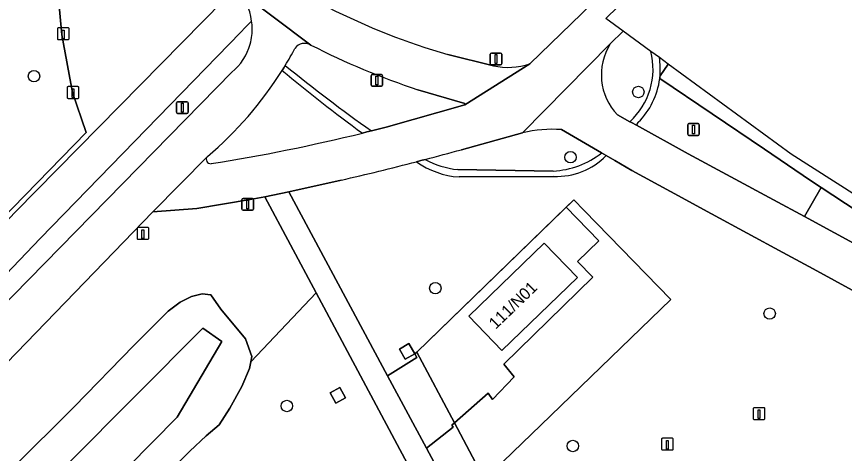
# Model space of a CAD drawing. Extents: x 155640 to 156811, y 382821 to 384049.
# Drawn here: x 156361.8 to 156432.6, y 383288.6 to 383326 of the extents above; entities that cross this region are included whole.
import ezdxf

# ---------------------------------------------------------------- set-up
doc = ezdxf.new("R2010")
doc.units = 0
for name, color, linetype in [('IMGEO_Berm_groen', 7, 'Continuous'), ('IMGEO_Boom', 7, 'Continuous'), ('IMGEO_Fietspad_gesloten', 7, 'Continuous'), ('IMGEO_Groenvoorziening', 7, 'Continuous'), ('IMGEO_Haag', 7, 'Continuous'), ('IMGEO_Hek', 7, 'Continuous'), ('IMGEO_Lichtmast', 7, 'Continuous'), ('IMGEO_Muur', 7, 'Continuous'), ('IMGEO_Oever', 7, 'Continuous'), ('IMGEO_Paal', 7, 'Continuous'), ('IMGEO_Pand', 7, 'Continuous'), ('IMGEO_Pand_nummerreeks', 7, 'Continuous'), ('IMGEO_Terreindeel_gesloten', 7, 'Continuous'), ('IMGEO_Verkeerseiland_groen', 7, 'Continuous'), ('IMGEO_Verkeerseiland_halfverhard', 7, 'Continuous'), ('IMGEO_Verkeerseiland_open', 7, 'Continuous'), ('IMGEO_Voetpad_gesloten', 7, 'Continuous'), ('IMGEO_Voetpad_onverhard', 7, 'Continuous'), ('IMGEO_Voetpad_open', 7, 'Continuous'), ('IMGEO_Waterloop', 7, 'Continuous')]:
    doc.layers.add(name, color=color, linetype=linetype)

msp = doc.modelspace()

# ---------------------------------------------------------------- linework, layer by layer
at = {"layer": 'IMGEO_Berm_groen'}
for points in [[(156381.892, 383325.599), (156381.348, 383325.039), (156380.959, 383324.639), (156363.82, 383307.004), (156337.443, 383279.37), (156311.15, 383251.521)], [(156360.181, 383300.803), (156380.194, 383321.217)], [(156361.434, 383287.344), (156366.724, 383292.604), (156371.834, 383297.853), (156374.748, 383300.784), (156375.78, 383301.56), (156376.759, 383302.039), (156377.674, 383302.264), (156378.399, 383302.193), (156379.248, 383300.961), (156381.369, 383298.415), (156381.897, 383296.903), (156381.815, 383296.443), (156387.41, 383302.346), (156383.014, 383310.578), (156381.78, 383310.334), (156377.211, 383309.584), (156373.432, 383309.293), (156346.778, 383281.729)]]:
    msp.add_lwpolyline(points, dxfattribs=at)
msp.add_lwpolyline([(156444.63, 383302.545), (156439.121, 383305.912), (156433.651, 383309.341), (156430.583, 383311.361), (156429.166, 383308.873), (156431.712, 383307.496), (156436.911, 383304.669), (156442.11, 383301.833), (156447.27, 383298.926), (156452.282, 383295.927), (156457.215, 383292.799), (156462.066, 383289.543), (156462.324, 383289.355), (156463.241, 383290.742), (156459.141, 383293.542), (156454.393, 383296.613), (156449.523, 383299.599)], close=True, dxfattribs=at)
for centre, radius, start, end in [((156377.156, 383324.92), 4.785, 353.42613, 8.16143), ((156377.193, 383324.912), 4.747, 344.44891, 353.47288), ((156377.133, 383324.925), 4.808, 309.53884, 344.48996)]:
    msp.add_arc(centre, radius, start, end, dxfattribs=at)
at = {"layer": 'IMGEO_Boom'}
for centre in [(156363.284, 383320.89), (156414.951, 383319.535), (156409.148, 383313.953), (156397.595, 383302.756), (156426.175, 383300.58), (156384.909, 383292.681), (156409.344, 383289.257)]:
    msp.add_circle(centre, 0.489, dxfattribs=at)
at = {"layer": 'IMGEO_Fietspad_gesloten'}
for points in [[(156413.66, 383324.737), (156412.178, 383325.823), (156505.069, 383416.138), (156504.846, 383416.367), (156503.871, 383417.37), (156412.253, 383328.349), (156411.874, 383327.981), (156405.667, 383321.95), (156400.124, 383318.442), (156393.394, 383316.534), (156392.135, 383316.212), (156391.748, 383316.116), (156391.361, 383316.02)], [(156363.724, 383341.638), (156369.095, 383337.403), (156379.009, 383329.585), (156379.648, 383329.081), (156380.504, 383328.406), (156386.96, 383323.552)], [(156386.96, 383323.552), (156380.504, 383328.406)], [(156399.819, 383314.599), (156405.049, 383316.037), (156412.539, 383323.648), (156413.66, 383324.737)], [(156412.539, 383323.648), (156405.049, 383316.037)], [(156402.557, 383321.777), (156398.667, 383322.745)], [(156396.11, 383319.733), (156400.129, 383318.562), (156400.124, 383318.442), (156405.667, 383321.95)], [(156380.194, 383321.217), (156360.181, 383300.803), (156343.328, 383283.312), (156320.142, 383258.454)], [(156384.5, 383321.375), (156384.634, 383321.592), (156384.768, 383321.81)], [(156471.432, 383282.388), (156466.787, 383286.102), (156462.324, 383289.355), (156462.066, 383289.543), (156457.215, 383292.799), (156452.282, 383295.927), (156447.27, 383298.926), (156442.11, 383301.833), (156436.911, 383304.669), (156431.712, 383307.496), (156429.166, 383308.873), (156426.506, 383310.311), (156419.216, 383314.26), (156414.78, 383316.686), (156414.359, 383316.916), (156414.222, 383316.991), (156413.154, 383317.575)], [(156408.386, 383316.322), (156411.813, 383314.329), (156412.207, 383314.099), (156412.93, 383313.678), (156414.393, 383312.827), (156417.685, 383311.033), (156421.201, 383309.128), (156427.301, 383305.816), (156429.889, 383304.414), (156435.055, 383301.593), (156440.217, 383298.767), (156445.339, 383295.87), (156450.27, 383292.91), (156455.125, 383289.825), (156459.799, 383286.696), (156464.349, 383283.389), (156469.029, 383279.65)], [(156322.635, 383255.833), (156346.778, 383281.729), (156373.432, 383309.293), (156378.108, 383314.02)], [(156378.108, 383314.02), (156373.432, 383309.293), (156377.211, 383309.584), (156381.78, 383310.334), (156383.014, 383310.578), (156385.084, 383310.986), (156389.538, 383311.991)], [(156395.984, 383313.573), (156396.356, 383313.67), (156396.729, 383313.767)]]:
    msp.add_lwpolyline(points, dxfattribs=at)
for centre, radius, start, end in [((156377.296, 383325.073), 4.626, 6.52779, 46.09498), ((156414.327, 383377.419), 56.872, 242.94269, 254.01676), ((156377.156, 383324.92), 4.785, 353.42613, 8.16143), ((156377.193, 383324.912), 4.747, 344.44891, 353.47288), ((156377.133, 383324.925), 4.808, 309.53884, 344.48996), ((156386.438, 383322.641), 1.05, 60.19021, 143.26914), ((156415.713, 383379.57), 62.966, 242.82975, 251.86117), ((156416.776, 383321.009), 4.992, 148.08972, 223.4753), ((156362.021, 383335.7), 26.653, 328.59089, 332.19886), ((156403.809, 383327.314), 5.676, 257.25954, 289.10828), ((156357.442, 383338.435), 31.988, 310.24597, 327.76827), ((156407.66, 383305.149), 11.196, 86.27976, 103.48336), ((156353.48, 383470.12), 158.687, 279.04397, 283.81086), ((156332.865, 383557.107), 251.581, 284.70542, 285.43422), ((156378.385, 383313.773), 0.371, 138.27225, 276.11786), ((156334.578, 383549.852), 244.128, 283.01029, 284.56809)]:
    msp.add_arc(centre, radius, start, end, dxfattribs=at)
at = {"layer": 'IMGEO_Groenvoorziening'}
for points in [[(156307.679, 383394.347), (156302.123, 383400.705), (156299.359, 383400.927), (156306.65, 383393.611), (156313.765, 383385.402), (156329.371, 383369.364), (156360.098, 383342.127), (156366.667, 383336.304), (156365.54, 383332.038), (156365.287, 383328.46), (156365.66, 383324.427), (156366.576, 383319.504), (156367.747, 383316.069), (156357.254, 383305.321), (156321.635, 383267.495), (156317.51, 383263.114), (156305.054, 383249.887), (156299.88, 383244.1), (156294.909, 383238.207), (156290.182, 383232.037), (156285.682, 383225.699), (156281.371, 383219.262), (156269.6, 383231.099)], [(156308.935, 383253.615), (156335.323, 383281.619), (156361.745, 383309.309), (156379.48, 383327.364), (156380.013, 383327.906), (156380.504, 383328.406), (156379.648, 383329.081), (156379.009, 383329.585), (156369.095, 383337.403), (156363.724, 383341.638)], [(156346.883, 383328.534), (156340.219, 383321.277), (156340.634, 383320.888), (156357.254, 383305.321), (156367.747, 383316.069), (156366.576, 383319.504), (156365.66, 383324.427), (156365.287, 383328.46)], [(156425.73, 383314.654), (156416.776, 383320.676)], [(156414.939, 383316.944), (156414.78, 383316.686), (156419.216, 383314.26), (156426.506, 383310.311), (156429.166, 383308.873), (156430.583, 383311.361), (156429.668, 383311.964), (156425.73, 383314.654)], [(156469.029, 383279.65), (156464.349, 383283.389), (156459.799, 383286.696), (156455.125, 383289.825), (156450.27, 383292.91), (156445.339, 383295.87), (156440.217, 383298.767), (156435.055, 383301.593), (156429.889, 383304.414), (156427.301, 383305.816), (156421.201, 383309.128), (156417.685, 383311.033), (156414.393, 383312.827), (156412.93, 383313.678), (156412.207, 383314.099)], [(156407.731, 383312.309), (156399.621, 383312.271)], [(156389.538, 383311.991), (156385.084, 383310.986), (156393.506, 383295.268), (156396.023, 383296.828), (156395.84, 383297.138), (156396, 383297.293), (156408.79, 383309.671), (156409.44, 383310.3), (156410.313, 383309.402), (156417.72, 383301.78), (156406.599, 383291.031), (156401.804, 383286.397), (156399.225, 383291.239), (156399.005, 383291.045), (156399.107, 383290.866), (156396.831, 383289.064), (156404.514, 383274.725)], [(156401.917, 383275.179), (156387.41, 383302.346), (156381.815, 383296.443), (156381.713, 383295.875), (156381.067, 383294.349), (156380.037, 383292.488), (156379.109, 383291.061), (156378.013, 383290.134), (156376.603, 383288.823), (156373.814, 383286.022), (156313.066, 383224.543), (156307.199, 383217.739), (156241.776, 383106.748)]]:
    msp.add_lwpolyline(points, dxfattribs=at)
for points in [[(156417.72, 383301.78), (156410.313, 383309.402), (156409.44, 383310.3), (156408.79, 383309.671), (156411.57, 383306.798), (156409.755, 383305.026), (156411.064, 383303.686), (156403.455, 383296.258), (156404.345, 383295.185), (156402.473, 383293.222), (156402.105, 383293.774), (156399.225, 383291.239), (156401.804, 383286.397), (156406.599, 383291.031)], [(156395.84, 383297.138), (156395.016, 383296.673), (156394.52, 383297.548), (156395.342, 383298.015)], [(156388.605, 383293.791), (156389.427, 383294.258), (156389.924, 383293.383), (156389.101, 383292.916)]]:
    msp.add_lwpolyline(points, close=True, dxfattribs=at)
for centre, radius, start, end in [((156410.444, 383321.475), 6.382, 314.77376, 352.81071), ((156334.578, 383549.852), 244.128, 283.01029, 284.56809), ((156400.077, 383319.277), 7.021, 234.33453, 266.27202), ((156407.902, 383318.372), 6.065, 268.38031, 315.21368)]:
    msp.add_arc(centre, radius, start, end, dxfattribs=at)
at = {"layer": 'IMGEO_Haag'}
msp.add_lwpolyline([(156414.939, 383316.944), (156414.78, 383316.686), (156419.216, 383314.26), (156426.506, 383310.311), (156429.166, 383308.873), (156430.583, 383311.361), (156429.668, 383311.964), (156425.73, 383314.654), (156416.776, 383320.676)], dxfattribs=at)
msp.add_arc((156410.444, 383321.475), 6.382, 314.77376, 352.81071, dxfattribs=at)
at = {"layer": 'IMGEO_Hek'}
for points in [[(156396, 383297.293), (156409.44, 383310.3)], [(156409.44, 383310.3), (156410.313, 383309.402)], [(156410.313, 383309.402), (156417.72, 383301.78), (156406.599, 383291.031)], [(156396, 383297.293), (156401.804, 383286.397)], [(156406.599, 383291.031), (156401.804, 383286.397)]]:
    msp.add_lwpolyline(points, dxfattribs=at)
at = {"layer": 'IMGEO_Lichtmast'}
for p, q in [((156402.288, 383321.96), (156402.288, 383322.76)), ((156402.288, 383322.76), (156402.288, 383321.96)), ((156402.388, 383322.86), (156403.178, 383322.86)), ((156403.178, 383322.86), (156402.388, 383322.86)), ((156403.278, 383322.76), (156403.278, 383321.96)), ((156403.278, 383321.96), (156403.278, 383322.76)), ((156403.178, 383321.86), (156402.388, 383321.86)), ((156402.388, 383321.86), (156403.178, 383321.86)), ((156392.1, 383320.122), (156392.1, 383320.922)), ((156392.1, 383320.922), (156392.1, 383320.122)), ((156392.2, 383321.022), (156392.99, 383321.022)), ((156392.99, 383321.022), (156392.2, 383321.022)), ((156393.09, 383320.922), (156393.09, 383320.122)), ((156393.09, 383320.122), (156393.09, 383320.922)), ((156392.99, 383320.022), (156392.2, 383320.022)), ((156392.2, 383320.022), (156392.99, 383320.022)), ((156375.467, 383317.796), (156375.467, 383318.596)), ((156375.467, 383318.596), (156375.467, 383317.796)), ((156375.567, 383318.696), (156376.357, 383318.696)), ((156376.357, 383318.696), (156375.567, 383318.696)), ((156376.457, 383318.596), (156376.457, 383317.796)), ((156376.457, 383317.796), (156376.457, 383318.596)), ((156376.357, 383317.696), (156375.567, 383317.696)), ((156375.567, 383317.696), (156376.357, 383317.696)), ((156419.167, 383315.927), (156419.167, 383316.727)), ((156419.167, 383316.727), (156419.167, 383315.927)), ((156419.267, 383316.827), (156420.057, 383316.827)), ((156420.057, 383316.827), (156419.267, 383316.827)), ((156420.157, 383316.727), (156420.157, 383315.927)), ((156420.157, 383315.927), (156420.157, 383316.727)), ((156420.057, 383315.827), (156419.267, 383315.827)), ((156419.267, 383315.827), (156420.057, 383315.827)), ((156381.062, 383309.519), (156381.062, 383310.319)), ((156381.062, 383310.319), (156381.062, 383309.519)), ((156381.162, 383310.419), (156381.952, 383310.419)), ((156381.952, 383310.419), (156381.162, 383310.419)), ((156382.052, 383310.319), (156382.052, 383309.519)), ((156382.052, 383309.519), (156382.052, 383310.319)), ((156381.952, 383309.419), (156381.162, 383309.419)), ((156381.162, 383309.419), (156381.952, 383309.419))]:
    msp.add_line(p, q, dxfattribs=at)
for points in [[(156402.708, 383322.735), (156402.858, 383322.735), (156402.858, 383321.985), (156402.708, 383321.985), (156402.708, 383322.735)], [(156392.52, 383320.897), (156392.67, 383320.897), (156392.67, 383320.147), (156392.52, 383320.147), (156392.52, 383320.897)], [(156375.887, 383318.571), (156376.037, 383318.571), (156376.037, 383317.821), (156375.887, 383317.821), (156375.887, 383318.571)], [(156419.587, 383316.702), (156419.737, 383316.702), (156419.737, 383315.952), (156419.587, 383315.952), (156419.587, 383316.702)], [(156381.482, 383310.294), (156381.632, 383310.294), (156381.632, 383309.544), (156381.482, 383309.544), (156381.482, 383310.294)]]:
    msp.add_lwpolyline(points, dxfattribs=at)
for centre, start, end in [((156402.388, 383322.76), 90, 180), ((156402.388, 383322.76), 90, 180), ((156403.178, 383322.76), 0, 90), ((156403.178, 383322.76), 360, 90), ((156402.388, 383321.96), 180, 270), ((156402.388, 383321.96), 180, 270), ((156403.178, 383321.96), 270, 0), ((156403.178, 383321.96), 270, 0), ((156392.2, 383320.922), 90, 180), ((156392.2, 383320.922), 90, 180), ((156392.99, 383320.922), 0, 90), ((156392.99, 383320.922), 360, 90), ((156392.2, 383320.122), 180, 270), ((156392.2, 383320.122), 180, 270), ((156392.99, 383320.122), 270, 0), ((156392.99, 383320.122), 270, 0), ((156375.567, 383318.596), 90, 180), ((156375.567, 383318.596), 90, 180), ((156376.357, 383318.596), 0, 90), ((156376.357, 383318.596), 360, 90), ((156375.567, 383317.796), 180, 270), ((156375.567, 383317.796), 180, 270), ((156376.357, 383317.796), 270, 0), ((156376.357, 383317.796), 270, 0), ((156419.267, 383316.727), 90, 180), ((156419.267, 383316.727), 90, 180), ((156420.057, 383316.727), 0, 90), ((156420.057, 383316.727), 360, 90), ((156419.267, 383315.927), 180, 270), ((156419.267, 383315.927), 180, 270), ((156420.057, 383315.927), 270, 0), ((156420.057, 383315.927), 270, 0), ((156381.162, 383310.319), 90, 180), ((156381.162, 383310.319), 90, 180), ((156381.952, 383310.319), 0, 90), ((156381.952, 383310.319), 360, 90), ((156381.162, 383309.519), 180, 270), ((156381.162, 383309.519), 180, 270), ((156381.952, 383309.519), 270, 0), ((156381.952, 383309.519), 270, 0)]:
    msp.add_arc(centre, 0.1, start, end, dxfattribs=at)
at = {"layer": 'IMGEO_Muur'}
for points in [[(156395.342, 383298.015), (156394.52, 383297.548), (156395.016, 383296.673), (156395.84, 383297.138)], [(156389.427, 383294.258), (156388.605, 383293.791), (156389.101, 383292.916), (156389.924, 383293.383)]]:
    msp.add_lwpolyline(points, close=True, dxfattribs=at)
at = {"layer": 'IMGEO_Oever'}
for points in [[(156313.066, 383224.543), (156373.814, 383286.022), (156376.603, 383288.823), (156378.013, 383290.134), (156379.109, 383291.061), (156380.037, 383292.488), (156381.067, 383294.349), (156381.713, 383295.875), (156381.815, 383296.443), (156381.897, 383296.903), (156381.369, 383298.415), (156379.248, 383300.961), (156378.399, 383302.193), (156377.674, 383302.264), (156376.759, 383302.039), (156375.78, 383301.56), (156374.748, 383300.784), (156371.834, 383297.853), (156366.724, 383292.604), (156361.434, 383287.344)], [(156314.169, 383235.475), (156377.724, 383299.338), (156379.347, 383298.182), (156375.527, 383291.728), (156309.837, 383225.147)]]:
    msp.add_lwpolyline(points, dxfattribs=at)
at = {"layer": 'IMGEO_Paal'}
for p, q in [((156365.288, 383324.932), (156365.288, 383324.091)), ((156365.288, 383324.932), (156365.288, 383324.091)), ((156366.204, 383325.016), (156365.363, 383325.016)), ((156366.204, 383325.016), (156365.363, 383325.016)), ((156366.288, 383324.1), (156366.288, 383324.941)), ((156366.288, 383324.1), (156366.288, 383324.941)), ((156365.372, 383324.016), (156366.213, 383324.016)), ((156365.372, 383324.016), (156366.213, 383324.016)), ((156366.125, 383319.908), (156366.125, 383319.067)), ((156366.125, 383319.908), (156366.125, 383319.067)), ((156367.041, 383319.992), (156366.2, 383319.992)), ((156367.041, 383319.992), (156366.2, 383319.992)), ((156367.125, 383319.076), (156367.125, 383319.917)), ((156367.125, 383319.076), (156367.125, 383319.917)), ((156366.209, 383318.992), (156367.05, 383318.992)), ((156366.209, 383318.992), (156367.05, 383318.992)), ((156372.099, 383307.854), (156372.099, 383307.013)), ((156372.099, 383307.854), (156372.099, 383307.013)), ((156373.015, 383307.938), (156372.174, 383307.938)), ((156373.015, 383307.938), (156372.174, 383307.938)), ((156373.099, 383307.022), (156373.099, 383307.863)), ((156373.099, 383307.022), (156373.099, 383307.863)), ((156372.183, 383306.938), (156373.024, 383306.938)), ((156372.183, 383306.938), (156373.024, 383306.938)), ((156424.763, 383292.443), (156424.763, 383291.602)), ((156424.763, 383292.443), (156424.763, 383291.602)), ((156425.679, 383292.527), (156424.838, 383292.527)), ((156425.679, 383292.527), (156424.838, 383292.527)), ((156425.763, 383291.611), (156425.763, 383292.452)), ((156425.763, 383291.611), (156425.763, 383292.452)), ((156424.847, 383291.527), (156425.688, 383291.527)), ((156424.847, 383291.527), (156425.688, 383291.527)), ((156416.935, 383289.833), (156416.935, 383288.992)), ((156416.935, 383289.833), (156416.935, 383288.992)), ((156417.851, 383289.917), (156417.01, 383289.917)), ((156417.851, 383289.917), (156417.01, 383289.917)), ((156417.935, 383289.001), (156417.935, 383289.842)), ((156417.935, 383289.001), (156417.935, 383289.842)), ((156417.019, 383288.917), (156417.86, 383288.917)), ((156417.019, 383288.917), (156417.86, 383288.917))]:
    msp.add_line(p, q, dxfattribs=at)
for points in [[(156365.703, 383324.829), (156365.863, 383324.829), (156365.863, 383324.096), (156365.703, 383324.096), (156365.703, 383324.829)], [(156366.54, 383319.805), (156366.7, 383319.805), (156366.7, 383319.072), (156366.54, 383319.072), (156366.54, 383319.805)], [(156372.514, 383307.751), (156372.674, 383307.751), (156372.674, 383307.018), (156372.514, 383307.018), (156372.514, 383307.751)], [(156425.178, 383292.34), (156425.338, 383292.34), (156425.338, 383291.607), (156425.178, 383291.607), (156425.178, 383292.34)], [(156417.35, 383289.73), (156417.51, 383289.73), (156417.51, 383288.997), (156417.35, 383288.997), (156417.35, 383289.73)]]:
    msp.add_lwpolyline(points, dxfattribs=at)
for centre, start, end in [((156365.366, 383324.938), 92.4484, 184.28452), ((156365.366, 383324.938), 92.4484, 184.28452), ((156366.21, 383324.938), 2.4484, 94.28452), ((156366.21, 383324.938), 2.4484, 94.28452), ((156365.366, 383324.094), 182.4484, 274.28452), ((156365.366, 383324.094), 182.4484, 274.28452), ((156366.21, 383324.094), 272.4484, 4.28452), ((156366.21, 383324.094), 272.4484, 4.28452), ((156366.203, 383319.914), 92.4484, 184.28452), ((156366.203, 383319.914), 92.4484, 184.28452), ((156367.047, 383319.914), 2.4484, 94.28452), ((156367.047, 383319.914), 2.4484, 94.28452), ((156366.203, 383319.07), 182.4484, 274.28452), ((156366.203, 383319.07), 182.4484, 274.28452), ((156367.047, 383319.07), 272.4484, 4.28452), ((156367.047, 383319.07), 272.4484, 4.28452), ((156372.177, 383307.86), 92.4484, 184.28452), ((156372.177, 383307.86), 92.4484, 184.28452), ((156373.021, 383307.86), 2.4484, 94.28452), ((156373.021, 383307.86), 2.4484, 94.28452), ((156372.177, 383307.016), 182.4484, 274.28452), ((156372.177, 383307.016), 182.4484, 274.28452), ((156373.021, 383307.016), 272.4484, 4.28452), ((156373.021, 383307.016), 272.4484, 4.28452), ((156424.841, 383292.449), 92.4484, 184.28452), ((156424.841, 383292.449), 92.4484, 184.28452), ((156425.685, 383292.449), 2.4484, 94.28452), ((156425.685, 383292.449), 2.4484, 94.28452), ((156424.841, 383291.605), 182.4484, 274.28452), ((156424.841, 383291.605), 182.4484, 274.28452), ((156425.685, 383291.605), 272.4484, 4.28452), ((156425.685, 383291.605), 272.4484, 4.28452), ((156417.013, 383289.839), 92.4484, 184.28452), ((156417.013, 383289.839), 92.4484, 184.28452), ((156417.857, 383289.839), 2.4484, 94.28452), ((156417.857, 383289.839), 2.4484, 94.28452), ((156417.013, 383288.995), 182.4484, 274.28452), ((156417.013, 383288.995), 182.4484, 274.28452), ((156417.857, 383288.995), 272.4484, 4.28452), ((156417.857, 383288.995), 272.4484, 4.28452)]:
    msp.add_arc(centre, 0.0779, start, end, dxfattribs=at)
at = {"layer": 'IMGEO_Pand'}
msp.add_lwpolyline([(156403.272, 383297.412), (156409.756, 383303.668), (156406.909, 383306.619), (156400.449, 383300.359)], close=True, dxfattribs=at)
at = {"layer": 'IMGEO_Terreindeel_gesloten'}
msp.add_lwpolyline([(156404.514, 383274.725), (156396.831, 383289.064), (156393.506, 383295.268), (156385.084, 383310.986), (156383.014, 383310.578), (156387.41, 383302.346), (156401.917, 383275.179)], dxfattribs=at)
at = {"layer": 'IMGEO_Verkeerseiland_groen'}
for centre, radius, start, end in [((156357.442, 383338.435), 31.988, 310.24597, 327.76827), ((156465.056, 383417.513), 125.426, 230.03972, 234.01632), ((156353.48, 383470.12), 158.687, 279.04397, 283.81086), ((156378.385, 383313.773), 0.371, 138.27225, 276.11786)]:
    msp.add_arc(centre, radius, start, end, dxfattribs=at)
at = {"layer": 'IMGEO_Verkeerseiland_halfverhard'}
for points in [[(156405.667, 383321.95), (156411.874, 383327.981), (156401.494, 383337.48)], [(156413.66, 383324.737), (156412.539, 383323.648)], [(156416.016, 383323.011), (156413.66, 383324.737)], [(156398.667, 383322.745), (156402.557, 383321.777)], [(156392.135, 383316.212), (156393.394, 383316.534), (156400.124, 383318.442), (156400.129, 383318.562), (156396.11, 383319.733)], [(156413.154, 383317.575), (156414.222, 383316.991)], [(156411.813, 383314.329), (156408.386, 383316.322)], [(156405.049, 383316.037), (156399.819, 383314.599)], [(156399.51, 383312.894), (156407.664, 383312.773)]]:
    msp.add_lwpolyline(points, dxfattribs=at)
for centre, radius, start, end in [((156414.327, 383377.419), 56.872, 242.94269, 254.01676), ((156386.438, 383322.641), 1.05, 60.19021, 143.26914), ((156415.713, 383379.57), 62.966, 242.82975, 251.86117), ((156416.776, 383321.009), 4.992, 148.08972, 223.4753), ((156362.021, 383335.7), 26.653, 328.59089, 332.19886), ((156410.097, 383321.498), 6.11, 312.46936, 14.33577), ((156403.809, 383327.314), 5.676, 257.25954, 289.10828), ((156465.596, 383420.533), 127.591, 230.69177, 234.84764), ((156407.66, 383305.149), 11.196, 86.27976, 103.48336), ((156332.865, 383557.107), 251.581, 284.70542, 285.43422), ((156407.309, 383320.03), 7.266, 272.804, 308.31112), ((156400.443, 383320.733), 7.895, 241.93421, 263.20999)]:
    msp.add_arc(centre, radius, start, end, dxfattribs=at)
at = {"layer": 'IMGEO_Verkeerseiland_open'}
for points in [[(156416.746, 383322.476), (156416.016, 383323.011)], [(156384.768, 383321.81), (156384.634, 383321.592), (156384.5, 383321.375)], [(156416.776, 383320.676), (156416.789, 383320.794), (156416.801, 383320.912)], [(156414.222, 383316.991), (156414.359, 383316.916), (156414.78, 383316.686), (156414.939, 383316.944)], [(156391.361, 383316.02), (156391.748, 383316.116), (156392.135, 383316.212)], [(156412.207, 383314.099), (156411.813, 383314.329)], [(156396.729, 383313.767), (156396.356, 383313.67), (156395.984, 383313.573)], [(156407.664, 383312.773), (156399.51, 383312.894)], [(156399.621, 383312.271), (156407.731, 383312.309)]]:
    msp.add_lwpolyline(points, dxfattribs=at)
for centre, radius, start, end in [((156410.097, 383321.498), 6.11, 312.46936, 14.33577), ((156410.444, 383321.472), 6.382, 354.96469, 9.04836), ((156465.056, 383417.513), 125.426, 230.03972, 234.01632), ((156465.596, 383420.533), 127.591, 230.69177, 234.84764), ((156410.444, 383321.475), 6.382, 314.77376, 352.81071), ((156407.309, 383320.03), 7.266, 272.804, 308.31112), ((156400.077, 383319.277), 7.021, 234.33453, 266.27202), ((156400.443, 383320.733), 7.895, 241.93421, 263.20999), ((156407.902, 383318.372), 6.065, 268.38031, 315.21368)]:
    msp.add_arc(centre, radius, start, end, dxfattribs=at)
at = {"layer": 'IMGEO_Voetpad_gesloten'}
for points in [[(156380.504, 383328.406), (156380.013, 383327.906), (156379.48, 383327.364), (156361.745, 383309.309), (156335.323, 383281.619), (156308.935, 383253.615)], [(156337.443, 383279.37), (156363.82, 383307.004), (156380.959, 383324.639), (156381.348, 383325.039), (156381.892, 383325.599)], [(156511.86, 383233.285), (156505.71, 383240.565), (156499.576, 383248.934), (156483.932, 383273.137), (156474.992, 383282.98), (156460.822, 383293.299), (156428.012, 383314.221), (156417.508, 383321.917), (156416.801, 383320.912), (156416.789, 383320.794), (156416.776, 383320.676), (156425.73, 383314.654), (156429.668, 383311.964), (156430.583, 383311.361), (156433.651, 383309.341), (156439.121, 383305.912), (156444.63, 383302.545), (156449.523, 383299.599), (156454.393, 383296.613), (156459.141, 383293.542), (156463.241, 383290.742), (156463.811, 383290.353), (156468.861, 383286.76)]]:
    msp.add_lwpolyline(points, dxfattribs=at)
msp.add_arc((156377.296, 383325.073), 4.626, 6.52779, 46.09498, dxfattribs=at)
at = {"layer": 'IMGEO_Voetpad_onverhard'}
for points in [[(156417.508, 383321.917), (156416.746, 383322.476)], [(156416.801, 383320.912), (156417.508, 383321.917)]]:
    msp.add_lwpolyline(points, dxfattribs=at)
msp.add_arc((156410.444, 383321.472), 6.382, 354.96469, 9.04836, dxfattribs=at)
at = {"layer": 'IMGEO_Voetpad_open'}
for points in [[(156408.79, 383309.671), (156396, 383297.293), (156399.225, 383291.239), (156402.105, 383293.774), (156402.473, 383293.222), (156404.345, 383295.185), (156403.455, 383296.258), (156411.064, 383303.686), (156409.755, 383305.026), (156411.57, 383306.798)], [(156400.449, 383300.359), (156406.909, 383306.619), (156409.756, 383303.668), (156403.272, 383297.412)], [(156396, 383297.293), (156395.84, 383297.138), (156396.023, 383296.828), (156393.506, 383295.268), (156396.831, 383289.064), (156399.107, 383290.866), (156399.005, 383291.045), (156399.225, 383291.239)]]:
    msp.add_lwpolyline(points, close=True, dxfattribs=at)
at = {"layer": 'IMGEO_Waterloop'}
msp.add_lwpolyline([(156309.837, 383225.147), (156375.527, 383291.728), (156379.347, 383298.182), (156377.724, 383299.338), (156314.169, 383235.475)], dxfattribs=at)

# ---------------------------------------------------------------- texts
at = {"layer": 'IMGEO_Pand_nummerreeks'}
msp.add_text('111/N01', height=1, rotation=44.00727, dxfattribs=at).set_placement((156402.752, 383299.193))

doc.saveas('drawing.dxf')
